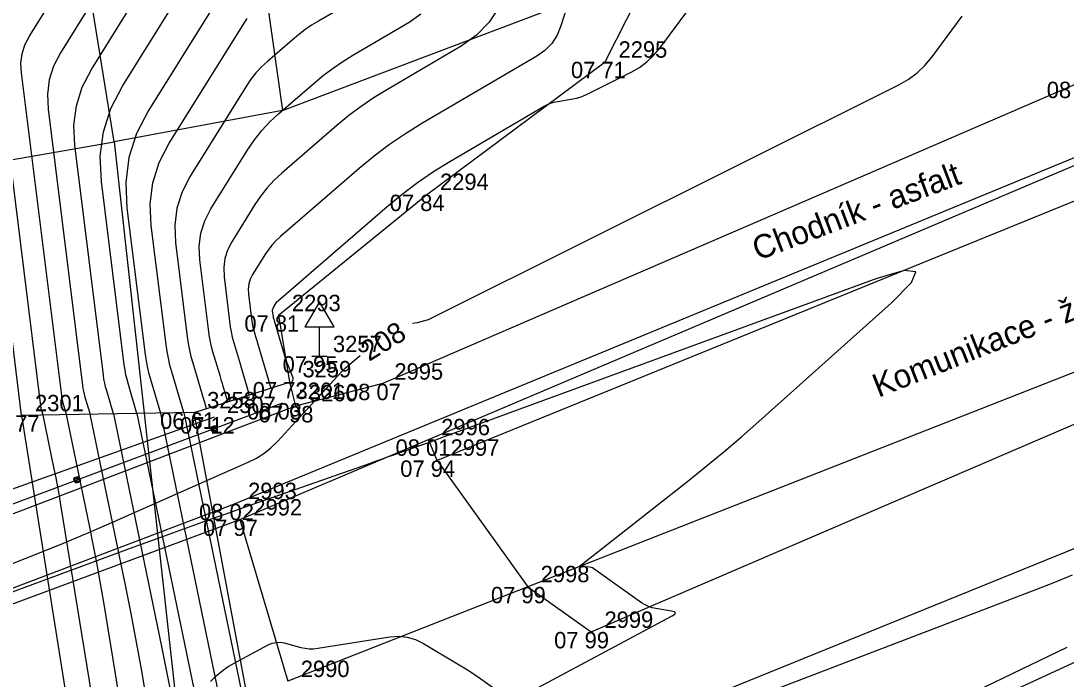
# Model space of a CAD drawing. Extents: x -703403 to -701924, y -1022520 to -1021856.
# Drawn here: x -702430.47 to -702412.61, y -1022313.64 to -1022302.4 of the extents above; entities that cross this region are included whole.
import ezdxf

# ---------------------------------------------------------------- set-up
doc = ezdxf.new("R2010")
doc.units = 0
for name, color, linetype in [('Ex_Contour Labels', 7, 'Continuous'), ('Ex_Major Contours', 7, 'Continuous'), ('Ex_Minor Contours', 7, 'Continuous'), ('Z_betonova_konstrukce', 7, 'Continuous'), ('Z_body', 7, 'Continuous'), ('Z_body_cisla', 7, 'Continuous'), ('Z_body_vysky_redukovane', 7, 'Continuous'), ('Z_chodnik', 7, 'Continuous'), ('Z_dopravni_znacky', 7, 'Continuous'), ('Z_hrany_paty', 7, 'Continuous'), ('Z_katastr_hranice', 7, 'Continuous'), ('Z_komunikace', 7, 'Continuous'), ('Z_komunikace_osa', 7, 'Continuous'), ('Z_obruba', 7, 'Continuous'), ('Z_popisy', 7, 'Continuous'), ('Z_produktovod07', 7, 'Continuous'), ('Z_rozhranni', 7, 'Continuous'), ('Z_vodni_tok', 7, 'Continuous'), ('Z_zabradli', 7, 'Continuous'), ('Z_zabradli_znaky', 7, 'Continuous')]:
    doc.layers.add(name, color=color, linetype=linetype)

# ---------------------------------------------------------------- blocks, each defined once
blk = doc.blocks.new('POINT_DISPLAY')
blk.add_line((0, 0), (0, 0))
blk = doc.blocks.new('Z527')
for p, q in [((0, 0.93), (-0.25, 0.5)), ((0.25, 0.5), (0, 0.93)), ((-0.25, 0.5), (0.25, 0.5)), ((0, 0), (0, 0.5)), ((-0.13, 0), (0.13, 0))]:
    blk.add_line(p, q)
blk = doc.blocks.new('Z530')
for p, q in [((-0.05, 0.03), (-0.03, 0.05)), ((-0.05, -0.03), (-0.05, 0.03)), ((-0.03, 0.05), (0.03, 0.05)), ((-0.03, -0.03), (-0.03, 0.03)), ((-0.03, 0.03), (0.03, 0.03)), ((-0.03, -0.03), (0.03, 0.03)), ((0.03, 0.05), (0.05, 0.03)), ((0.03, 0.03), (0.03, -0.03)), ((0.05, 0.03), (0.05, -0.03)), ((-0.03, -0.05), (-0.05, -0.03)), ((0.03, -0.03), (-0.03, -0.03)), ((0.03, -0.05), (-0.03, -0.05)), ((0.05, -0.03), (0.03, -0.05))]:
    blk.add_line(p, q)

msp = doc.modelspace()

# ---------------------------------------------------------------- linework, layer by layer
at = {"layer": 'Ex_Major Contours'}
for points in [[(-702428.488, -1022309.107), (-702428.635, -1022308.613), (-702428.658, -1022308.53), (-702428.677, -1022308.447), (-702428.693, -1022308.363), (-702428.705, -1022308.278), (-702429.097, -1022305.142), (-702429.115, -1022304.711), (-702429.062, -1022304.296), (-702428.936, -1022303.897), (-702428.738, -1022303.514), (-702427.802, -1022302.013)], [(-702426.937, -1022308.907), (-702427.016, -1022308.64), (-702427.029, -1022308.595), (-702427.042, -1022308.551), (-702427.055, -1022308.506), (-702427.068, -1022308.461), (-702427.19, -1022308.052), (-702427.213, -1022307.968), (-702427.233, -1022307.884), (-702427.249, -1022307.799), (-702427.261, -1022307.714), (-702427.415, -1022306.481), (-702427.425, -1022306.251), (-702427.396, -1022306.03), (-702427.329, -1022305.817), (-702427.224, -1022305.613), (-702426.592, -1022304.6), (-702426.479, -1022304.433), (-702426.354, -1022304.275), (-702426.218, -1022304.128), (-702426.07, -1022303.99), (-702425.455, -1022303.459), (-702425.299, -1022303.33), (-702425.138, -1022303.208), (-702424.97, -1022303.094), (-702424.798, -1022302.988), (-702423.837, -1022302.425), (-702423.637, -1022302.283)], [(-702423.782, -1022307.567), (-702423.694, -1022307.552), (-702423.632, -1022307.539), (-702423.57, -1022307.522), (-702423.51, -1022307.5), (-702423.452, -1022307.473), (-702415.473, -1022303.494), (-702415.309, -1022303.401), (-702415.16, -1022303.29), (-702415.025, -1022303.162), (-702414.904, -1022303.018), (-702414.387, -1022302.323)], [(-702430.091, -1022309.134), (-702430.119, -1022309.041), (-702430.123, -1022309.026), (-702430.127, -1022309.01), (-702430.13, -1022308.995), (-702430.132, -1022308.979), (-702430.919, -1022302.673)], [(-702421.878, -1022313.922), (-702419.342, -1022312.566), (-702419.298, -1022312.537), (-702419.286, -1022312.514), (-702419.305, -1022312.495), (-702419.356, -1022312.482), (-702419.622, -1022312.441), (-702419.687, -1022312.428), (-702419.749, -1022312.407), (-702419.808, -1022312.378), (-702419.865, -1022312.343), (-702420.682, -1022311.76), (-702420.705, -1022311.746), (-702420.73, -1022311.736), (-702420.756, -1022311.731), (-702420.783, -1022311.729), (-702420.894, -1022311.731), (-702420.916, -1022311.73), (-702420.925, -1022311.723), (-702420.922, -1022311.713), (-702420.906, -1022311.698), (-702419.078, -1022310.263), (-702418.767, -1022310.016), (-702418.462, -1022309.763), (-702418.16, -1022309.506), (-702417.862, -1022309.244), (-702415.597, -1022307.215), (-702415.256, -1022306.87), (-702415.183, -1022306.686), (-702415.38, -1022306.663), (-702415.845, -1022306.802), (-702423.283, -1022309.526), (-702423.386, -1022309.564), (-702423.489, -1022309.601), (-702423.592, -1022309.638), (-702423.695, -1022309.674), (-702424.108, -1022309.82), (-702424.212, -1022309.856), (-702424.315, -1022309.892), (-702424.418, -1022309.929), (-702424.522, -1022309.965), (-702426.375, -1022310.615), (-702426.579, -1022310.686), (-702426.784, -1022310.759), (-702426.988, -1022310.831), (-702427.192, -1022310.904), (-702428.008, -1022311.197), (-702428.212, -1022311.27), (-702428.416, -1022311.344), (-702428.62, -1022311.419), (-702428.823, -1022311.493), (-702431.565, -1022312.505)], [(-702430.618, -1022311.669), (-702430.18, -1022311.498), (-702429.745, -1022311.322), (-702429.311, -1022311.141), (-702428.88, -1022310.954), (-702426.586, -1022309.941), (-702426.448, -1022309.872), (-702426.319, -1022309.789), (-702426.199, -1022309.694), (-702426.088, -1022309.585), (-702425.585, -1022309.038), (-702425.453, -1022308.896), (-702425.322, -1022308.753), (-702425.06, -1022308.468), (-702424.993, -1022308.398), (-702424.924, -1022308.33), (-702424.853, -1022308.265), (-702424.779, -1022308.202), (-702424.677, -1022308.116)], [(-702428.18, -1022320.645), (-702428.189, -1022320.512), (-702428.191, -1022320.49), (-702428.193, -1022320.468), (-702428.196, -1022320.446), (-702428.199, -1022320.424), (-702429.787, -1022310.67), (-702429.813, -1022310.515), (-702429.841, -1022310.361), (-702429.87, -1022310.207), (-702429.901, -1022310.054), (-702430.091, -1022309.134)], [(-702428.488, -1022309.107), (-702427.305, -1022314.831), (-702427.221, -1022315.249), (-702427.141, -1022315.668), (-702427.066, -1022316.088), (-702426.995, -1022316.509), (-702426.619, -1022318.823), (-702426.603, -1022318.93), (-702426.589, -1022319.036), (-702426.578, -1022319.143), (-702426.569, -1022319.251), (-702426.524, -1022319.895)], [(-702412.507, -1022311.867), (-702412.813, -1022311.995), (-702413.121, -1022312.117), (-702424.616, -1022316.515), (-702424.625, -1022316.518), (-702424.635, -1022316.519), (-702424.645, -1022316.519), (-702424.655, -1022316.516), (-702424.694, -1022316.503), (-702424.704, -1022316.5), (-702424.714, -1022316.499), (-702424.724, -1022316.5), (-702424.734, -1022316.503), (-702428.623, -1022317.913), (-702429.017, -1022318.006), (-702429.242, -1022317.939), (-702429.298, -1022317.71), (-702429.206, -1022317.395)], [(-702427.231, -1022313.684), (-702427.137, -1022313.591), (-702427.037, -1022313.507), (-702426.93, -1022313.432), (-702426.816, -1022313.365), (-702426.245, -1022313.059), (-702426.179, -1022313.031), (-702426.112, -1022313.017), (-702426.043, -1022313.016), (-702425.973, -1022313.028), (-702425.688, -1022313.104), (-702425.617, -1022313.119), (-702425.545, -1022313.126), (-702425.473, -1022313.126), (-702425.4, -1022313.118), (-702424.167, -1022312.924), (-702424.016, -1022312.912), (-702423.87, -1022312.927), (-702423.729, -1022312.968), (-702423.593, -1022313.035), (-702422.983, -1022313.4), (-702422.889, -1022313.457), (-702422.796, -1022313.517), (-702422.704, -1022313.578), (-702422.613, -1022313.642), (-702422.253, -1022313.898)]]:
    msp.add_lwpolyline(points, dxfattribs=at)
at = {"layer": 'Ex_Minor Contours'}
for points in [[(-702425.868, -1022308.617), (-702425.827, -1022308.539), (-702425.822, -1022308.526), (-702425.82, -1022308.512), (-702425.821, -1022308.499), (-702425.825, -1022308.485), (-702425.911, -1022308.271), (-702425.927, -1022308.23), (-702425.941, -1022308.189), (-702425.955, -1022308.148), (-702425.968, -1022308.107), (-702426.138, -1022307.525), (-702426.146, -1022307.501), (-702426.153, -1022307.476), (-702426.155, -1022307.47), (-702426.156, -1022307.464), (-702426.157, -1022307.457), (-702426.158, -1022307.451), (-702426.17, -1022307.36), (-702426.17, -1022307.343), (-702426.168, -1022307.326), (-702426.163, -1022307.311), (-702426.155, -1022307.295), (-702426.113, -1022307.227), (-702426.102, -1022307.212), (-702426.091, -1022307.197), (-702426.078, -1022307.183), (-702426.064, -1022307.17), (-702424.213, -1022305.57), (-702423.958, -1022305.359), (-702423.695, -1022305.161), (-702423.422, -1022304.976), (-702423.141, -1022304.802), (-702421.541, -1022303.864), (-702421.484, -1022303.834), (-702421.424, -1022303.809), (-702421.363, -1022303.79), (-702421.3, -1022303.777), (-702421.043, -1022303.733), (-702420.979, -1022303.72), (-702420.917, -1022303.702), (-702420.857, -1022303.68), (-702420.798, -1022303.653), (-702420.042, -1022303.276), (-702419.902, -1022303.196), (-702419.775, -1022303.102), (-702419.66, -1022302.993), (-702419.557, -1022302.87), (-702417.668, -1022300.328)], [(-702426.674, -1022301.337), (-702428.292, -1022303.93), (-702428.495, -1022304.324), (-702428.625, -1022304.734), (-702428.68, -1022305.16), (-702428.66, -1022305.603), (-702428.348, -1022308.102), (-702428.333, -1022308.205), (-702428.314, -1022308.306), (-702428.291, -1022308.406), (-702428.264, -1022308.506), (-702428.087, -1022309.1)], [(-702421.029, -1022301.808), (-702421.244, -1022302.486), (-702421.31, -1022302.645), (-702421.401, -1022302.785), (-702421.517, -1022302.905), (-702421.657, -1022303.004), (-702423.622, -1022304.155), (-702423.902, -1022304.328), (-702424.173, -1022304.513), (-702424.436, -1022304.711), (-702424.69, -1022304.92), (-702426.038, -1022306.085), (-702426.11, -1022306.153), (-702426.176, -1022306.225), (-702426.237, -1022306.302), (-702426.292, -1022306.383), (-702426.512, -1022306.735), (-702426.552, -1022306.813), (-702426.578, -1022306.894), (-702426.589, -1022306.979), (-702426.585, -1022307.067), (-702426.526, -1022307.539), (-702426.521, -1022307.571), (-702426.515, -1022307.604), (-702426.508, -1022307.636), (-702426.499, -1022307.668), (-702426.461, -1022307.795), (-702426.442, -1022307.859), (-702426.423, -1022307.923), (-702426.203, -1022308.673)], [(-702429.244, -1022302.061), (-702429.796, -1022302.947), (-702429.913, -1022303.173), (-702429.987, -1022303.408), (-702430.019, -1022303.653), (-702430.008, -1022303.907), (-702429.418, -1022308.628), (-702429.411, -1022308.679), (-702429.402, -1022308.729), (-702429.39, -1022308.778), (-702429.377, -1022308.827), (-702429.29, -1022309.12)], [(-702428.889, -1022309.113), (-702429.006, -1022308.72), (-702429.024, -1022308.654), (-702429.039, -1022308.588), (-702429.052, -1022308.521), (-702429.062, -1022308.453), (-702429.552, -1022304.525), (-702429.567, -1022304.182), (-702429.524, -1022303.852), (-702429.424, -1022303.535), (-702429.267, -1022303.23), (-702428.523, -1022302.037)], [(-702424.726, -1022302.017), (-702425.386, -1022302.404), (-702425.505, -1022302.477), (-702425.62, -1022302.556), (-702425.731, -1022302.639), (-702425.838, -1022302.728), (-702426.26, -1022303.093), (-702426.362, -1022303.188), (-702426.456, -1022303.289), (-702426.542, -1022303.397), (-702426.619, -1022303.512), (-702427.58, -1022305.052), (-702427.718, -1022305.32), (-702427.806, -1022305.598), (-702427.843, -1022305.888), (-702427.83, -1022306.188), (-702427.629, -1022307.801), (-702427.612, -1022307.913), (-702427.592, -1022308.024), (-702427.566, -1022308.135), (-702427.536, -1022308.244), (-702427.352, -1022308.864), (-702427.337, -1022308.912), (-702427.304, -1022309.024)], [(-702429.69, -1022309.127), (-702429.748, -1022308.934), (-702429.757, -1022308.902), (-702429.764, -1022308.869), (-702429.77, -1022308.837), (-702429.775, -1022308.803), (-702430.463, -1022303.29), (-702430.471, -1022303.124), (-702430.45, -1022302.964), (-702430.402, -1022302.811), (-702430.325, -1022302.663), (-702429.965, -1022302.085)], [(-702422.299, -1022302.161), (-702422.469, -1022302.422), (-702422.686, -1022302.646), (-702422.949, -1022302.833), (-702424.21, -1022303.572), (-702424.436, -1022303.711), (-702424.655, -1022303.861), (-702424.868, -1022304.02), (-702425.073, -1022304.19), (-702426.011, -1022305.001), (-702426.142, -1022305.122), (-702426.262, -1022305.253), (-702426.372, -1022305.391), (-702426.472, -1022305.539), (-702426.868, -1022306.174), (-702426.941, -1022306.315), (-702426.987, -1022306.462), (-702427.007, -1022306.615), (-702427, -1022306.774), (-702426.894, -1022307.626), (-702426.885, -1022307.685), (-702426.874, -1022307.744), (-702426.86, -1022307.802), (-702426.845, -1022307.86), (-702426.776, -1022308.09), (-702426.759, -1022308.147), (-702426.742, -1022308.205), (-702426.725, -1022308.262), (-702426.708, -1022308.32), (-702426.57, -1022308.79)], [(-702427.686, -1022309.093), (-702427.893, -1022308.398), (-702427.925, -1022308.282), (-702427.952, -1022308.165), (-702427.974, -1022308.047), (-702427.992, -1022307.927), (-702428.245, -1022305.896), (-702428.261, -1022305.524), (-702428.215, -1022305.166), (-702428.107, -1022304.822), (-702427.936, -1022304.491), (-702426.647, -1022302.425), (-702426.604, -1022302.362)], [(-702427.766, -1022320.458), (-702427.784, -1022320.197), (-702427.787, -1022320.153), (-702427.792, -1022320.11), (-702427.797, -1022320.067), (-702427.804, -1022320.024), (-702429.056, -1022312.332), (-702429.111, -1022312.01), (-702429.168, -1022311.688), (-702429.229, -1022311.367), (-702429.294, -1022311.047), (-702429.69, -1022309.127)], [(-702427.352, -1022320.27), (-702427.379, -1022319.881), (-702427.384, -1022319.817), (-702427.391, -1022319.752), (-702427.399, -1022319.688), (-702427.409, -1022319.624), (-702428.325, -1022313.995), (-702428.408, -1022313.505), (-702428.496, -1022313.016), (-702428.588, -1022312.527), (-702428.686, -1022312.04), (-702429.29, -1022309.12)], [(-702428.889, -1022309.113), (-702428.068, -1022313.087), (-702427.942, -1022313.714), (-702427.822, -1022314.343), (-702427.709, -1022314.973), (-702427.603, -1022315.604), (-702427.014, -1022319.224), (-702427.001, -1022319.309), (-702426.99, -1022319.394), (-702426.981, -1022319.48), (-702426.974, -1022319.566), (-702426.938, -1022320.083)], [(-702428.087, -1022309.1), (-702426.543, -1022316.576), (-702426.501, -1022316.785), (-702426.461, -1022316.994), (-702426.423, -1022317.204), (-702426.388, -1022317.415), (-702426.218, -1022318.455), (-702426.201, -1022318.567), (-702426.187, -1022318.679), (-702426.175, -1022318.791), (-702426.166, -1022318.903), (-702426.121, -1022319.556), (-702426.119, -1022319.579), (-702426.118, -1022319.602), (-702426.114, -1022319.672)], [(-702427.686, -1022309.093), (-702425.824, -1022318.108), (-702425.804, -1022318.214), (-702425.788, -1022318.321), (-702425.776, -1022318.428), (-702425.767, -1022318.536), (-702425.729, -1022319.184)], [(-702424.308, -1022317.375), (-702423.126, -1022318.038), (-702423.121, -1022318.04), (-702423.116, -1022318.043), (-702423.111, -1022318.045), (-702423.106, -1022318.047), (-702423.085, -1022318.054), (-702423.08, -1022318.055), (-702423.075, -1022318.055), (-702423.07, -1022318.055), (-702423.065, -1022318.053), (-702422.401, -1022317.799), (-702422.289, -1022317.755), (-702422.178, -1022317.709), (-702422.068, -1022317.66), (-702421.959, -1022317.609), (-702412.594, -1022313.099)]]:
    msp.add_lwpolyline(points, dxfattribs=at)
at = {"layer": 'Z_betonova_konstrukce'}
for p, q in [((-702427.51, -1022309.09), (-702425.88, -1022308.57)), ((-702425.88, -1022308.57), (-702425.78, -1022308.98)), ((-702425.78, -1022308.98), (-702437.85, -1022313.59)), ((-702427.51, -1022309.09), (-702430.46, -1022309.14)), ((-702425.78, -1022318.32), (-702427.51, -1022309.09))]:
    msp.add_line(p, q, dxfattribs=at)
at = {"layer": 'Z_chodnik'}
for q in [(-702412.36, -1022303.44), (-702425.78, -1022308.98)]:
    msp.add_line((-702424.31, -1022308.6), q, dxfattribs=at)
at = {"layer": 'Z_hrany_paty'}
for p, q in [((-702420.49, -1022303.1), (-702418.44, -1022299.06)), ((-702423.54, -1022305.37), (-702420.49, -1022303.1)), ((-702426.07, -1022307.43), (-702423.54, -1022305.37)), ((-702426.07, -1022307.43), (-702425.88, -1022308.57)), ((-702422.95, -1022318.18), (-702409.74, -1022312.1))]:
    msp.add_line(p, q, dxfattribs=at)
at = {"layer": 'Z_katastr_hranice'}
for p, q in [((-702428.88, -1022304.47), (-702436.49, -1022256.83)), ((-702432.63, -1022257.46), (-702426, -1022303.93)), ((-702426, -1022303.93), (-702383.14, -1022287.72)), ((-702426, -1022303.93), (-702428.88, -1022304.47)), ((-702431.67, -1022304.95), (-702428.88, -1022304.47)), ((-702428.88, -1022304.47), (-702426.78, -1022323.39))]:
    msp.add_line(p, q, dxfattribs=at)
at = {"layer": 'Z_komunikace'}
for p, q in [((-702423.51, -1022309.55), (-702411.93, -1022304.64)), ((-702426.73, -1022310.92), (-702423.51, -1022309.55)), ((-702424.76, -1022316.4), (-702410.18, -1022310.48)), ((-702431.61, -1022312.73), (-702426.73, -1022310.92))]:
    msp.add_line(p, q, dxfattribs=at)
at = {"layer": 'Z_komunikace_osa'}
for p, q in [((-702410.63, -1022307.68), (-702421.81, -1022312.07)), ((-702421.81, -1022312.07), (-702425.91, -1022313.68))]:
    msp.add_line(p, q, dxfattribs=at)
at = {"layer": 'Z_obruba'}
for p, q in [((-702426.82, -1022310.65), (-702411.98, -1022304.53)), ((-702431.72, -1022312.51), (-702426.82, -1022310.65))]:
    msp.add_line(p, q, dxfattribs=at)
at = {"layer": 'Z_produktovod07'}
msp.add_line((-702427.17, -1022309.17), (-702436.94, -1022312.65), dxfattribs=at)
at = {"layer": 'Z_rozhranni'}
for p, q in [((-702411.74, -1022305.18), (-702423.36, -1022309.91)), ((-702420.73, -1022312.84), (-702410.98, -1022308.65)), ((-702423.36, -1022309.91), (-702423.51, -1022309.55)), ((-702423.36, -1022309.91), (-702421.81, -1022312.07)), ((-702426.73, -1022310.92), (-702425.91, -1022313.68)), ((-702421.81, -1022312.07), (-702420.73, -1022312.84))]:
    msp.add_line(p, q, dxfattribs=at)
at = {"layer": 'Z_vodni_tok'}
for q in [(-702431.32, -1022302.13), (-702428.61, -1022320.84)]:
    msp.add_line((-702430.46, -1022309.14), q, dxfattribs=at)
at = {"layer": 'Z_zabradli'}
msp.add_line((-702426, -1022308.93), (-702437.78, -1022313.34), dxfattribs=at)

# ---------------------------------------------------------------- block references
at = {"layer": 'Z_body'}
for p in [(-702420.49, -1022303.1), (-702423.54, -1022305.37), (-702426.07, -1022307.43), (-702425.37, -1022308.13), (-702425.88, -1022308.57), (-702424.31, -1022308.6), (-702426, -1022308.93), (-702425.78, -1022308.98), (-702430.46, -1022309.14), (-702427.51, -1022309.09), (-702427.17, -1022309.17), (-702423.51, -1022309.55), (-702423.36, -1022309.91), (-702426.82, -1022310.65), (-702426.73, -1022310.92), (-702421.81, -1022312.07), (-702420.73, -1022312.84)]:
    msp.add_blockref('POINT_DISPLAY', p, dxfattribs=at)
at = {"layer": 'Z_dopravni_znacky'}
msp.add_blockref('Z527', (-702425.37, -1022308.13), dxfattribs=at)
at = {"layer": 'Z_zabradli_znaky', "rotation": 20.5}
for p in [(-702427.17, -1022309.37), (-702429.51, -1022310.24)]:
    msp.add_blockref('Z530', p, dxfattribs=at)

# ---------------------------------------------------------------- texts
at = {"layer": 'Ex_Contour Labels'}
msp.add_text('208', height=0.35, rotation=31.637, dxfattribs=at).set_placement((-702424.523, -1022308.227))
at = {"layer": 'Z_body_cisla'}
for s, p in [('2295', (-702420.26, -1022303.03)), ('2294', (-702423.31, -1022305.29)), ('2293', (-702425.84, -1022307.36)), ('3257', (-702425.14, -1022308.06)), ('3259', (-702425.66, -1022308.49)), ('2995', (-702424.09, -1022308.53)), ('3261', (-702425.78, -1022308.86)), ('3260', (-702425.55, -1022308.9)), ('2301', (-702430.23, -1022309.07)), ('3258', (-702427.29, -1022309.02)), ('2507', (-702426.95, -1022309.1)), ('2996', (-702423.29, -1022309.48)), ('2997', (-702423.13, -1022309.83)), ('2993', (-702426.59, -1022310.57)), ('2992', (-702426.5, -1022310.85)), ('2998', (-702421.59, -1022311.99)), ('2999', (-702420.5, -1022312.77)), ('2990', (-702425.69, -1022313.61))]:
    msp.add_text(s, height=0.28, dxfattribs=at).set_placement(p)
at = {"layer": 'Z_body_vysky_redukovane'}
for s, p in [('07 71', (-702421.073, -1022303.38)), ('08 15', (-702412.943, -1022303.72)), ('07 84', (-702424.17, -1022305.65)), ('07 81', (-702426.653, -1022307.71)), ('07 95', (-702426, -1022308.41)), ('07 72', (-702426.51, -1022308.85)), ('08 07', (-702424.917, -1022308.88)), ('08 03', (-702426.607, -1022309.21)), ('07 98', (-702426.41, -1022309.26)), ('04 77', (-702431.09, -1022309.42)), ('06 61', (-702428.093, -1022309.37)), ('07 12', (-702427.753, -1022309.45)), ('08 01', (-702424.07, -1022309.83)), ('07 94', (-702423.99, -1022310.19)), ('08 02', (-702427.427, -1022310.93)), ('07 97', (-702427.36, -1022311.2)), ('07 99', (-702422.44, -1022312.35)), ('07 99', (-702421.36, -1022313.12))]:
    msp.add_text(s, height=0.28, dxfattribs=at).set_placement(p)
at = {"layer": 'Z_popisy'}
for s, rotation, p in [('Chodník - asfalt', 20.7, (-702417.88, -1022306.5)), ('Komunikace - žulová dlažba', 21.6, (-702415.82, -1022308.84))]:
    msp.add_text(s, height=0.4, rotation=rotation, dxfattribs=at).set_placement(p)

doc.saveas('drawing.dxf')
